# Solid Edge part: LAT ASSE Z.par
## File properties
Subject: LAT ASSE Z
Author: f_grande
Template: Normal.par
Last saved by: f_grande
Revision: 17
Application: Solid Edge
Material: MDF
Stile della faccia: Marroncino
Coef. of Thermal Exp: 0.0
Thermal Conductivity: 0.0
Specific Heat: 0.0
Modulus of Elasticity: 0.0
Poisson's Ratio: 0.0
Yield Stress: 0.0
Ultimate Stress: 0.0
Elongation: 0.0
Tipo di contenuto documento: 0
Densità: 750,000 kg/m^3
Precisione: 0,990
Document Number: KR0121
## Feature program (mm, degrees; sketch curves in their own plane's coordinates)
sketch for "unnamed Protrusion 1" plane through (0, 0, 0) normal (0, -1, 0) x-axis (1, 0, 0)
  line (92.5285, 477.7051) -> (-45.4715, 477.7051)
  line (-106.4715, 384.7051) -> (-45.4715, 477.7051)
  line (-106.4715, 384.7051) -> (-106.4715, 349.7051)
  line (-106.4715, 349.7051) -> (32.5285, 349.7051)
  line (32.5285, 402.7051) -> (32.5285, 349.7051)
  line (92.5285, 427.7051) -> (32.5285, 402.7051)
  line (92.5285, 477.7051) -> (92.5285, 427.7051)
  dimension (linear) = 92.5285
  dimension (linear) = 106.4715
extrude "unnamed Protrusion 1" add finite 19 along +normal
sketch for "Foro_1" plane through (25.7098, -19, 217.2051) normal (0, -1, 0) x-axis (1, 0, 0)
  hole centre (-98.7813, 132.5) bore radius 14
hole "Foro_1" diameter 28 through
body pattern "unnamed BodyPattern 1"
pattern "unnamed Pattern 1"
sketch for "unnamed Cutout 1" plane through (-6.9715, -19, 349.7051) normal (0, -1, 0) x-axis (1, 0, 0)
extrude "unnamed Cutout 1" cut to key point along -normal
sketch for "ExtrudedCutout_2" plane through (-6.9715, -19, 349.7051) normal (0, -1, 0) x-axis (1, 0, 0)
extrude "ExtrudedCutout_2" cut finite 10 along -normal
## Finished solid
Body 1: solid body, 19 faces, 46 edges, 28 vertices.
  Faces by surface: plane 15, cylinder 4
  Edges by curve: line 38, circle 8
Bounding box of the edges (mm): 199.000 x 19.000 x 256.000, from (-106.4715, -19, 221.7051) to (92.5285, 0, 477.7051).
Cylindrical faces by radius (mm): R14 x1, R24 x1, R26 x2
Planar faces by outward normal: +x 4, +y 1, +z 1, -x 2, -y 2, -z 1, oblique 4
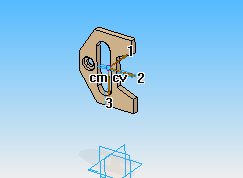
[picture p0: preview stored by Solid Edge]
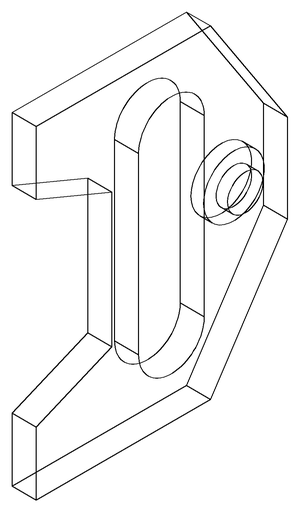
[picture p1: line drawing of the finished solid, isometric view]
